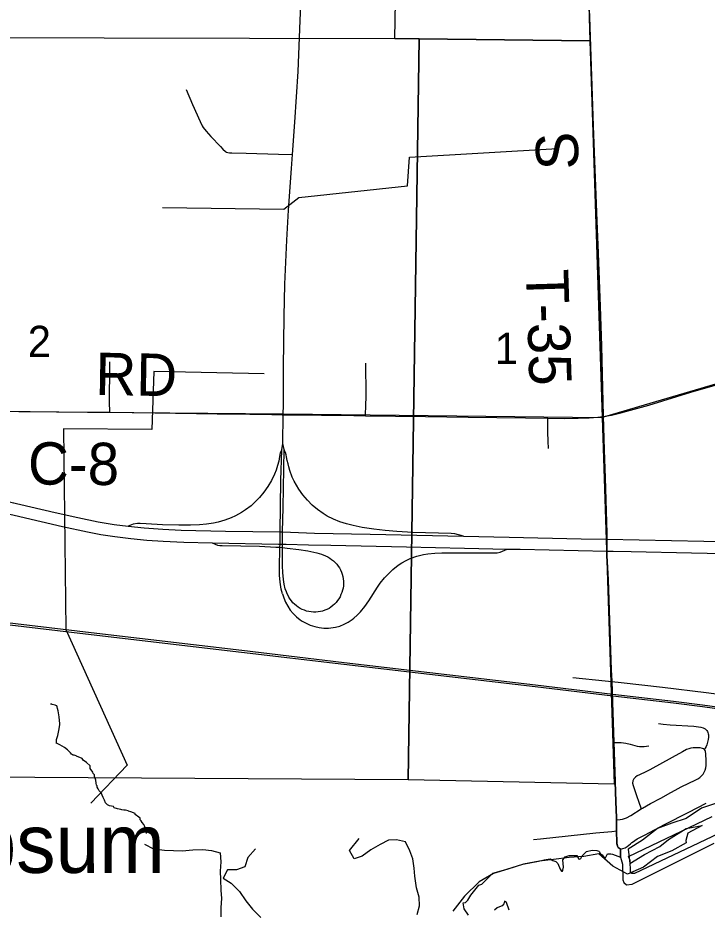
# Model space of a CAD drawing. Extents: x 63.4 to 97.4, y 0.4 to 22.4.
# Drawn here: x 67.186 to 68.112, y 15.396 to 16.594 of the extents above; entities that cross this region are included whole.
import ezdxf

# ---------------------------------------------------------------- set-up
doc = ezdxf.new("R2010")
doc.units = 0
for name, color, linetype in [('GM_X_County_Road', 7, 'Continuous'), ('GM_X_County_Road_Text', 7, 'Continuous'), ('GM_X_Interchange_Ramps', 7, 'Continuous'), ('GM_X_Major_Lake', 7, 'Continuous'), ('GM_X_Minor_River', 7, 'Continuous'), ('GM_X_Rail_Line', 7, 'Continuous'), ('GM_X_Section', 7, 'Continuous'), ('GM_X_Section_Text', 7, 'Continuous'), ('GM_X_State_Route', 7, 'Continuous'), ('GM_X_Township_Road', 7, 'Continuous'), ('GM_X_Township_Road_Text', 7, 'Continuous'), ('GM_X_Unincorporated_Text', 7, 'Continuous'), ('SH_Cut_Line', 7, 'Continuous')]:
    doc.layers.add(name, color=color, linetype=linetype)

msp = doc.modelspace()

# ---------------------------------------------------------------- linework, layer by layer
at = {"layer": 'GM_X_County_Road'}
for points in [[(67.7914, 15.3899), (67.7854, 15.3981), (67.7843, 15.4062), (67.7872, 15.4069), (67.7903, 15.4097), (67.7946, 15.4168), (67.8052, 15.4302), (67.8091, 15.4313), (67.8147, 15.4366), (67.8242, 15.446), (67.8431, 15.4517), (67.8644, 15.4581), (67.8856, 15.4623), (67.8932, 15.4641), (67.9011, 15.4652), (67.9045, 15.4632), (67.9061, 15.4629), (67.9088, 15.4618), (67.9112, 15.4591), (67.9143, 15.4515), (67.9161, 15.4489), (67.9176, 15.4488), (67.9182, 15.4502), (67.9188, 15.4544), (67.918, 15.4642), (67.921, 15.4681), (67.9266, 15.4698), (67.9369, 15.4699), (67.9376, 15.4685), (67.9392, 15.4655), (67.9405, 15.4648), (67.9424, 15.466), (67.944, 15.4694), (67.9497, 15.4754), (67.9576, 15.4771), (67.9639, 15.4764), (67.9663, 15.4757), (67.9672, 15.4747), (67.9681, 15.4725), (67.9708, 15.4709), (67.9735, 15.4673), (67.9749, 15.466), (67.9762, 15.4685), (67.978, 15.4723), (67.9825, 15.4723), (67.9849, 15.4715), (67.9953, 15.4677), (67.9954, 15.479), (67.9937, 15.4797), (67.9925, 15.4806), (67.9916, 15.4824), (67.9909, 15.4844), (67.9905, 15.4862), (67.9905, 15.488), (67.9903, 15.5018), (67.9903, 15.5034), (67.9902, 15.5183), (67.9902, 15.5204), (67.9892, 15.5422), (67.9866, 15.6219), (67.9849, 15.6757), (67.9838, 15.7038), (67.9831, 15.7192), (67.9813, 15.772), (67.979, 15.8401), (67.9773, 15.872), (67.9773, 15.8791), (67.9771, 15.895), (67.977, 15.9024), (67.9748, 15.9769), (67.9736, 16.0142), (67.9722, 16.0597), (67.9698, 16.154), (67.9682, 16.2068), (67.9653, 16.2782), (67.9637, 16.3217), (67.9589, 16.449), (67.9575, 16.4894), (67.954, 16.595)], [(67.954, 16.595), (67.9575, 16.4894), (67.9589, 16.449), (67.9637, 16.3217), (67.9653, 16.2782), (67.9682, 16.2068), (67.9698, 16.154), (67.9722, 16.0597), (67.9736, 16.0142), (67.9748, 15.9769), (67.977, 15.9024), (67.9771, 15.895), (67.9773, 15.8791), (67.9773, 15.872), (67.979, 15.8401), (67.9813, 15.772), (67.9831, 15.7192), (67.9838, 15.7038), (67.9849, 15.6757), (67.9866, 15.6219), (67.9892, 15.5422), (67.9902, 15.5204), (67.9902, 15.5183), (67.9903, 15.5034), (67.9903, 15.5018), (67.9905, 15.488), (67.9905, 15.4862), (67.9909, 15.4844), (67.9916, 15.4824), (67.9925, 15.4806), (67.9937, 15.4797), (67.9954, 15.479), (67.9953, 15.4677), (67.9984, 15.4584), (67.9986, 15.4373), (67.9999, 15.4336), (68.0036, 15.4304), (68.0113, 15.4313), (68.1213, 15.4865)], [(67.9724, 16.0591), (67.9774, 16.0599), (67.9835, 16.0611), (67.9961, 16.064), (68.0088, 16.0675), (68.0336, 16.0744), (68.09, 16.0918), (68.1165, 16.0994), (68.1264, 16.1022)], [(66.9594, 16.0695), (66.9875, 16.0692), (67.087, 16.0673), (67.2799, 16.0651), (67.3097, 16.0648)], [(67.3097, 16.0648), (67.3421, 16.0644), (67.4541, 16.0627), (67.4976, 16.0624), (67.5132, 16.0621), (67.5412, 16.0615), (67.5426, 16.0615)], [(67.5426, 16.0615), (67.594, 16.0609), (67.6376, 16.0604), (67.653, 16.0601)], [(67.653, 16.0601), (67.7335, 16.0591), (67.7908, 16.0584), (67.8679, 16.0574), (67.8979, 16.057)], [(67.8979, 16.057), (67.9204, 16.0566), (67.9388, 16.0567), (67.9534, 16.0573), (67.9649, 16.0583), (67.9724, 16.0591)], [(68.1268, 15.4988), (68.0141, 15.4455), (68.0109, 15.4455), (68.0088, 15.4478), (68.0086, 15.4633), (68.0063, 15.4683), (68.1184, 15.5224)], [(67.8462, 15.3963), (67.8426, 15.4066), (67.8398, 15.4087), (67.8387, 15.4048), (67.8366, 15.4023), (67.8331, 15.4009), (67.8299, 15.3995), (67.8264, 15.3963)]]:
    msp.add_lwpolyline(points, dxfattribs=at)
at = {"layer": 'GM_X_Interchange_Ramps'}
for points in [[(67.5407, 16.0143), (67.5387, 16.0105), (67.5377, 16.0054), (67.5366, 15.9993), (67.5351, 15.9932), (67.5332, 15.9873), (67.531, 15.9815), (67.5269, 15.973), (67.522, 15.965), (67.5166, 15.9574), (67.5106, 15.9502), (67.5041, 15.9435), (67.4994, 15.9394), (67.4919, 15.9338), (67.4867, 15.9303), (67.4785, 15.9258), (67.4728, 15.9231), (67.4641, 15.9198), (67.4551, 15.9173), (67.449, 15.916), (67.4397, 15.9147), (67.4304, 15.9139), (67.4179, 15.9134), (67.4023, 15.9133), (67.3805, 15.9139), (67.3587, 15.915), (67.3507, 15.9156), (67.3469, 15.9157), (67.3413, 15.9147), (67.3343, 15.9118)], [(67.7848, 15.8983), (67.773, 15.9015), (67.768, 15.9021), (67.7168, 15.9034), (67.6951, 15.9046), (67.6796, 15.9059), (67.6641, 15.9078), (67.6488, 15.9102), (67.6366, 15.9127), (67.6275, 15.915), (67.6187, 15.9178), (67.61, 15.9213), (67.6017, 15.9255), (67.5964, 15.9287), (67.5888, 15.9341), (67.5817, 15.9402), (67.5751, 15.9468), (67.5691, 15.9539), (67.5636, 15.9615), (67.5604, 15.9668), (67.5574, 15.9723), (67.5548, 15.9779), (67.5515, 15.9866), (67.5501, 15.9914), (67.5491, 15.9956), (67.5481, 16.0002), (67.5471, 16.0048), (67.5464, 16.0078), (67.5458, 16.0108), (67.5449, 16.0123), (67.5437, 16.0146)], [(67.5415, 15.821), (67.5433, 15.8156), (67.5457, 15.8098), (67.5486, 15.8044), (67.5521, 15.7992), (67.556, 15.7945), (67.5604, 15.7901), (67.5653, 15.7862), (67.5679, 15.7845), (67.5733, 15.7815), (67.579, 15.779), (67.5849, 15.7771), (67.5909, 15.7758), (67.5971, 15.7751), (67.6033, 15.7751), (67.6064, 15.7753), (67.6126, 15.7763), (67.6185, 15.7779), (67.6243, 15.7802), (67.6298, 15.7831), (67.635, 15.7865), (67.6374, 15.7884), (67.642, 15.7925), (67.6464, 15.797), (67.6522, 15.8042), (67.6575, 15.8119), (67.6694, 15.8302), (67.673, 15.8353), (67.6788, 15.8426), (67.6829, 15.8472), (67.6896, 15.8536), (67.6969, 15.8594), (67.7021, 15.8628), (67.7075, 15.8659), (67.7131, 15.8685), (67.7219, 15.8717), (67.7309, 15.8738), (67.737, 15.8748), (67.7463, 15.8757), (67.7556, 15.876), (67.7711, 15.8763), (67.8299, 15.8762), (67.8338, 15.877), (67.8433, 15.8812)]]:
    msp.add_lwpolyline(points, dxfattribs=at)
at = {"layer": 'GM_X_Major_Lake'}
for points in [[(68.1242, 15.5399), (68.1041, 15.5334), (68.0836, 15.5195), (68.0646, 15.5131), (68.0452, 15.506), (68.0251, 15.4905)], [(68.06, 15.4912), (68.0836, 15.506), (68.1052, 15.5099), (68.0858, 15.4996), (68.0832, 15.4902)], [(68.06, 15.4912), (68.0836, 15.506), (68.1052, 15.5099), (68.0858, 15.4996), (68.0832, 15.4902)], [(68.0832, 15.4902), (68.0837, 15.4869), (68.0643, 15.4761), (68.0453, 15.4686), (68.0263, 15.4542), (68.0047, 15.445), (67.9853, 15.4557), (67.9664, 15.4723), (67.9462, 15.4684)], [(68.0832, 15.4902), (68.0837, 15.4869), (68.0643, 15.4761), (68.0453, 15.4686), (68.0263, 15.4542), (68.0047, 15.445), (67.9853, 15.4557), (67.9664, 15.4723), (67.9462, 15.4684)], [(68.0251, 15.4905), (68.0058, 15.4784), (68.008, 15.4592), (68.0278, 15.4714), (68.0483, 15.4819), (68.06, 15.4912)], [(67.9462, 15.4684), (67.9264, 15.4672), (67.9056, 15.4645), (67.8866, 15.4623), (67.8653, 15.4581), (67.8441, 15.4516), (67.8251, 15.4459), (67.8057, 15.4345), (67.786, 15.4151), (67.7704, 15.3953)]]:
    msp.add_lwpolyline(points, dxfattribs=at)
at = {"layer": 'GM_X_Minor_River'}
for points in [[(67.3804, 16.3395), (67.5433, 16.3372), (67.5637, 16.3533), (67.7094, 16.3688), (67.7123, 16.4072), (67.9108, 16.4188)], [(67.5171, 16.1163), (67.369, 16.1194), (67.366, 16.0415), (67.2475, 16.0424), (67.2508, 15.773), (67.3329, 15.5913), (67.2842, 15.5401)], [(67.3592, 15.4992), (67.3588, 15.5015), (67.3581, 15.5034), (67.3581, 15.5045), (67.3574, 15.5068), (67.3563, 15.5095), (67.3556, 15.5114), (67.3533, 15.5141), (67.3519, 15.5164), (67.3507, 15.5179), (67.3504, 15.5198), (67.347, 15.5225), (67.3455, 15.5237), (67.344, 15.5248), (67.3437, 15.526), (67.338, 15.5283), (67.335, 15.5292), (67.3342, 15.5299), (67.3308, 15.5307), (67.3286, 15.5308), (67.3259, 15.5312), (67.3244, 15.5316), (67.3202, 15.5324), (67.3157, 15.534), (67.3146, 15.5355), (67.3093, 15.5367), (67.3067, 15.5379), (67.3055, 15.5391), (67.3041, 15.5406), (67.3026, 15.544), (67.3007, 15.5479), (67.2982, 15.554), (67.2956, 15.5567), (67.2941, 15.5594), (67.293, 15.5616), (67.2926, 15.5632), (67.2919, 15.5643), (67.2915, 15.567), (67.2908, 15.5708), (67.2901, 15.5735), (67.289, 15.5761), (67.2891, 15.578), (67.2876, 15.58), (67.2868, 15.5819), (67.2835, 15.5865), (67.2832, 15.5903), (67.2783, 15.5949), (67.2738, 15.598), (67.2727, 15.5999), (67.2652, 15.6031), (67.2648, 15.6038), (67.2618, 15.6046), (67.2606, 15.6046), (67.2603, 15.605), (67.2595, 15.605), (67.2584, 15.6058), (67.2569, 15.6077), (67.2558, 15.6089), (67.2531, 15.6116), (67.249, 15.6147), (67.2426, 15.6186), (67.2392, 15.6201), (67.2377, 15.6205), (67.2381, 15.6213), (67.2382, 15.6255), (67.2398, 15.6311), (67.2414, 15.6376), (67.2418, 15.6398), (67.2427, 15.6455), (67.2427, 15.6467), (67.2417, 15.6562), (67.2403, 15.6642), (67.2396, 15.6672), (67.2392, 15.6695), (67.2385, 15.6707), (67.2381, 15.6707), (67.2362, 15.6718), (67.2324, 15.6726), (67.2317, 15.673), (67.2302, 15.6731)], [(67.7224, 15.3905), (67.7257, 15.4022), (67.7252, 15.414), (67.7217, 15.4263), (67.7193, 15.4419), (67.7184, 15.453), (67.7168, 15.4652), (67.7125, 15.4763), (67.7067, 15.4882), (67.6949, 15.4908), (67.6839, 15.4903), (67.6727, 15.4848), (67.6604, 15.4775), (67.6488, 15.469), (67.6377, 15.4654), (67.6318, 15.4766), (67.6447, 15.4927)], [(67.3565, 15.485), (67.3686, 15.479), (67.383, 15.4772), (67.3952, 15.4765), (67.407, 15.4763), (67.4211, 15.4775), (67.4348, 15.4779), (67.4461, 15.4765), (67.4579, 15.4736), (67.4587, 15.4614), (67.4581, 15.4489), (67.4582, 15.4375), (67.459, 15.4234), (67.4596, 15.412), (67.4589, 15.4002), (67.459, 15.3876)], [(67.5056, 15.479), (67.495, 15.4671), (67.4909, 15.4546), (67.4798, 15.4507), (67.468, 15.4506), (67.4621, 15.4393), (67.4729, 15.4326), (67.4841, 15.4217), (67.4926, 15.409), (67.5015, 15.3977), (67.5126, 15.3868)]]:
    msp.add_lwpolyline(points, dxfattribs=at)
at = {"layer": 'GM_X_Rail_Line'}
for points in [[(65.5072, 16.0914), (66.1191, 16.083), (66.4239, 16.0787), (66.8313, 16.0688), (67.543, 16.0626), (67.9702, 16.0577), (68.6101, 16.2463), (69.1053, 16.3972), (70.1929, 16.7393), (70.2646, 16.7591), (70.3642, 16.7634), (70.5898, 16.7764), (70.6857, 16.8302), (70.7827, 16.8988), (71.2174, 17.2501), (71.5086, 17.4876), (71.6576, 17.6039), (72.13, 17.975), (72.3072, 18.116)], [(66.467, 15.8627), (66.8611, 15.8179), (66.9571, 15.8051), (67.0056, 15.7998), (67.2846, 15.7667), (67.4867, 15.743), (67.6241, 15.7268), (67.881, 15.6968), (67.9851, 15.6843), (68.0666, 15.6747), (68.1054, 15.67), (68.1409, 15.665)], [(66.4673, 15.865), (66.8614, 15.8202), (66.9574, 15.8074), (67.0058, 15.8021), (67.2848, 15.769), (67.487, 15.7453), (67.6243, 15.7291), (67.8813, 15.6991), (67.9854, 15.6866), (68.0669, 15.677), (68.1057, 15.6723), (68.1412, 15.6673)]]:
    msp.add_lwpolyline(points, dxfattribs=at)
at = {"layer": 'GM_X_Section'}
for points in [[(67.9257, 17.5727), (67.9544, 16.5634), (67.725, 16.5661), (67.6925, 16.5663), (67.711, 17.573)], [(67.725, 16.5661), (67.7104, 15.5714), (66.7072, 15.5775), (66.716, 16.5687), (67.6925, 16.5663)], [(67.9544, 16.5634), (67.987, 15.5655), (67.7104, 15.5714), (67.725, 16.5661)]]:
    msp.add_lwpolyline(points, close=True, dxfattribs=at)
at = {"layer": 'GM_X_State_Route'}
for p, q in [((67.4473, 15.8897), (67.5363, 15.8878)), ((67.5417, 15.8638), (67.5418, 15.883)), ((67.5467, 15.8876), (67.5766, 15.887)), ((67.5766, 15.887), (67.6065, 15.8863))]:
    msp.add_line(p, q, dxfattribs=at)
for points in [[(67.555, 16.4107), (67.5582, 16.4541), (67.5625, 16.5224), (67.5653, 16.5907), (67.5665, 16.6218), (67.568, 16.6653), (67.574, 16.8332), (67.5756, 16.8673), (67.5777, 16.9233), (67.5801, 16.9792), (67.5803, 16.984)], [(67.5426, 16.0615), (67.5428, 16.0752), (67.5428, 16.0908), (67.5431, 16.125), (67.5439, 16.1934), (67.5449, 16.2369), (67.5473, 16.2959), (67.5497, 16.3362), (67.5537, 16.3921), (67.555, 16.4107)], [(65.6038, 16.2956), (65.6724, 16.2794), (65.7663, 16.2577), (65.9296, 16.2191), (66.0598, 16.1888), (66.329, 16.126), (66.3474, 16.1217), (66.4927, 16.0876), (66.7984, 16.0161), (66.9588, 15.9785), (66.986, 15.9721), (67.2462, 15.9113), (67.2796, 15.9042), (67.2979, 15.9007), (67.3163, 15.8979), (67.3379, 15.8952), (67.3595, 15.8931), (67.3812, 15.8916), (67.4091, 15.8905), (67.4473, 15.8897)], [(66.4824, 16.1066), (66.9589, 15.9953), (67.0548, 15.9729), (67.1244, 15.9564), (67.2365, 15.9302), (67.2668, 15.9234), (67.2943, 15.9179), (67.3158, 15.9143), (67.3343, 15.9118), (67.356, 15.9097), (67.3809, 15.9078), (67.4058, 15.9067), (67.4649, 15.9054), (67.5385, 15.9041), (67.5418, 15.9041), (67.5848, 15.9026), (67.6594, 15.901), (67.7848, 15.8983)], [(67.5418, 15.8835), (67.5418, 15.885), (67.5418, 15.8877), (67.5418, 15.9041), (67.5425, 15.9368), (67.5437, 16.0146), (67.5421, 16.0227), (67.5426, 16.0615)], [(67.5415, 15.821), (67.5399, 15.8275), (67.5385, 15.8367), (67.5378, 15.846), (67.5376, 15.8553), (67.5382, 15.8835), (67.5383, 15.8878), (67.5384, 15.8926), (67.5385, 15.9041), (67.5395, 15.9733), (67.5407, 16.0143), (67.5421, 16.0227)], [(67.7848, 15.8983), (67.8461, 15.897), (67.9426, 15.8951), (67.9773, 15.8944)], [(67.9773, 15.8944), (68.1074, 15.8917), (68.1945, 15.8897)], [(67.4473, 15.8897), (67.4545, 15.8864), (67.4573, 15.886), (67.4607, 15.886), (67.5108, 15.885), (67.5326, 15.8839), (67.5382, 15.8835), (67.5418, 15.8833), (67.5481, 15.8826), (67.5635, 15.8808), (67.5757, 15.8786), (67.5879, 15.876), (67.5939, 15.8743), (67.5996, 15.872), (67.6024, 15.8706), (67.6051, 15.869), (67.6076, 15.8673), (67.61, 15.8653), (67.6123, 15.8632), (67.6144, 15.8609), (67.6163, 15.8584), (67.618, 15.8558), (67.6195, 15.8531), (67.6208, 15.8503), (67.6218, 15.8474), (67.6226, 15.8444), (67.6232, 15.8413), (67.6235, 15.8382), (67.6235, 15.8351), (67.6234, 15.832), (67.6229, 15.8289), (67.6222, 15.8259), (67.6213, 15.8229), (67.6202, 15.82), (67.6189, 15.8172), (67.6173, 15.8145), (67.6156, 15.812), (67.6136, 15.8095), (67.6115, 15.8073), (67.6092, 15.8052), (67.6067, 15.8033), (67.6041, 15.8016), (67.6013, 15.8002), (67.5985, 15.799), (67.5955, 15.798), (67.5925, 15.7972), (67.5895, 15.7968), (67.5864, 15.7965), (67.5833, 15.7965), (67.5802, 15.7968), (67.5771, 15.7973), (67.5741, 15.798), (67.5711, 15.799), (67.5682, 15.8002), (67.5655, 15.8016), (67.5628, 15.8032), (67.5603, 15.805), (67.5579, 15.807), (67.5557, 15.8092), (67.5537, 15.8115), (67.5518, 15.814), (67.5502, 15.8166), (67.5474, 15.8222), (67.5469, 15.8236), (67.5453, 15.828), (67.5438, 15.834), (67.5428, 15.8402), (67.542, 15.8495), (67.5417, 15.8588), (67.5417, 15.8638)], [(67.5363, 15.8878), (67.5383, 15.8878), (67.5418, 15.8877), (67.5467, 15.8876)], [(67.6065, 15.8863), (67.708, 15.8842), (67.7859, 15.8824), (67.8433, 15.8812)], [(67.8433, 15.8812), (67.8606, 15.8809), (67.9775, 15.8785), (67.9856, 15.8783)], [(67.9856, 15.8783), (68.01, 15.8778), (68.0909, 15.8761), (68.1968, 15.8738), (68.2092, 15.8735), (68.2404, 15.8723), (68.259, 15.8711), (68.2777, 15.8691), (68.2962, 15.8664), (68.3115, 15.8637), (68.3298, 15.8599), (68.348, 15.8554), (68.366, 15.8503), (68.3838, 15.8444), (68.4014, 15.8379), (68.4187, 15.8308), (68.4357, 15.823), (68.4524, 15.8146), (68.4689, 15.8057), (68.4824, 15.7976)]]:
    msp.add_lwpolyline(points, dxfattribs=at)
at = {"layer": 'GM_X_Township_Road'}
msp.add_line((67.9905, 15.5028), (67.9904, 15.5178), dxfattribs=at)
for points in [[(67.9724, 16.0591), (67.97, 16.1534), (67.9685, 16.2062), (67.9655, 16.2776), (67.9639, 16.3211), (67.9591, 16.4484), (67.9577, 16.4888), (67.9542, 16.5944), (67.9516, 16.6658), (67.9465, 16.8211), (67.9429, 16.9112), (67.9401, 16.9982), (67.9376, 17.0851), (67.9356, 17.1597), (67.9321, 17.2995), (67.9309, 17.3399), (67.9304, 17.3555)], [(67.4122, 16.498), (67.421, 16.478), (67.4309, 16.4551), (67.4337, 16.4495), (67.4353, 16.4469), (67.4391, 16.4419), (67.4455, 16.4351), (67.4584, 16.4215), (67.4617, 16.4178), (67.4649, 16.415), (67.4666, 16.4139), (67.4684, 16.4133), (67.4707, 16.4131), (67.4738, 16.413), (67.4928, 16.4125), (67.5365, 16.4112), (67.555, 16.4107)], [(67.3097, 16.0648), (67.3095, 16.0787), (67.3094, 16.085), (67.3098, 16.1194), (67.3098, 16.1323)], [(67.653, 16.0601), (67.6532, 16.0631), (67.6536, 16.0721), (67.6539, 16.0877), (67.6535, 16.1306)], [(67.8988, 16.0162), (67.8983, 16.0258), (67.8979, 16.0382), (67.8979, 16.057)], [(67.984, 15.7033), (67.9833, 15.7187), (67.9815, 15.7714), (67.9793, 15.8395), (67.9776, 15.8714), (67.9775, 15.8785), (67.9773, 15.8944), (67.9772, 15.9018), (67.975, 15.9764), (67.9738, 16.0136), (67.9724, 16.0591)], [(67.9316, 15.7088), (67.9748, 15.7042), (67.984, 15.7033)], [(67.9852, 15.6731), (67.9851, 15.6752), (67.984, 15.7033)], [(67.984, 15.7033), (67.9965, 15.702), (68.0521, 15.6957), (68.1107, 15.6887), (68.1445, 15.684), (68.1629, 15.6807), (68.2633, 15.6598), (68.288, 15.6545)], [(67.9904, 15.5178), (67.9904, 15.5199), (67.9894, 15.5416), (67.9869, 15.6214), (67.9852, 15.6731)], [(68.0467, 15.647), (68.0529, 15.646), (68.0623, 15.6451), (68.0939, 15.6434), (68.1002, 15.6427), (68.1033, 15.6421), (68.1063, 15.6411), (68.1091, 15.6397), (68.1105, 15.6387), (68.1114, 15.6376), (68.1123, 15.6364), (68.1129, 15.6349), (68.1134, 15.6333), (68.1136, 15.6318), (68.1136, 15.6286), (68.1132, 15.6255), (68.1125, 15.6218), (68.1114, 15.6186), (68.1105, 15.6162), (68.1093, 15.6139), (68.1081, 15.612)], [(67.9869, 15.6214), (67.9931, 15.6214), (67.9963, 15.6214), (67.9994, 15.6211), (68.0025, 15.6206), (68.0087, 15.6192), (68.0148, 15.6175), (68.0179, 15.6168), (68.021, 15.6163), (68.0241, 15.6161), (68.0273, 15.6162), (68.0304, 15.6166), (68.0335, 15.6172)], [(68.1081, 15.612), (68.1071, 15.6128), (68.1057, 15.6136), (68.1027, 15.6143), (68.0995, 15.6145), (68.0932, 15.6143), (68.0901, 15.6139), (68.0871, 15.6131), (68.0842, 15.612), (68.0786, 15.6091), (68.0651, 15.6014), (68.035, 15.5849), (68.0294, 15.5821), (68.0208, 15.5782), (68.0181, 15.5767), (68.0155, 15.5749), (68.0134, 15.5726), (68.012, 15.5699), (68.0117, 15.5669), (68.0123, 15.5638), (68.0174, 15.549), (68.0196, 15.5428), (68.0234, 15.5325)], [(68.0234, 15.5325), (68.025, 15.5335), (68.0358, 15.5397), (68.0497, 15.5468), (68.0632, 15.5546), (68.0687, 15.5577), (68.0769, 15.5621), (68.0967, 15.5713), (68.0995, 15.5728), (68.102, 15.5746), (68.1043, 15.5767), (68.1063, 15.5791), (68.108, 15.5817), (68.1092, 15.5846), (68.1101, 15.5876), (68.1105, 15.5907), (68.1105, 15.597), (68.1102, 15.6064), (68.1097, 15.6095), (68.109, 15.6108), (68.1081, 15.612)], [(67.9957, 15.4785), (67.9988, 15.4791), (68.0017, 15.4802), (68.0044, 15.4819), (68.0066, 15.4835), (68.0089, 15.4853), (68.0109, 15.4873), (68.0128, 15.4888), (68.0149, 15.4902), (68.0177, 15.4921), (68.0288, 15.4978), (68.0546, 15.5113), (68.0874, 15.528), (68.1105, 15.5401)], [(67.9904, 15.5178), (67.995, 15.5183), (67.998, 15.5186), (67.9995, 15.5189), (68.0008, 15.5193), (68.0037, 15.5205), (68.0092, 15.5235), (68.0234, 15.5325)], [(67.8787, 15.4914), (67.888, 15.4922), (67.9623, 15.5002), (67.984, 15.5022), (67.9905, 15.5028)], [(67.9957, 15.4785), (67.9939, 15.4792), (67.9927, 15.48), (67.9918, 15.4819), (67.9911, 15.4839), (67.9907, 15.4857), (67.9907, 15.4874), (67.9905, 15.5012), (67.9905, 15.5028)]]:
    msp.add_lwpolyline(points, dxfattribs=at)
at = {"layer": 'SH_Cut_Line'}
for points in [[(68.1268, 15.4988), (68.0141, 15.4455), (68.0109, 15.4455), (68.0088, 15.4478), (68.0086, 15.4633), (68.0063, 15.4683), (68.1184, 15.5224)], [(67.7914, 15.3899), (67.7854, 15.3981), (67.7843, 15.4062), (67.7872, 15.4069), (67.7903, 15.4097), (67.7946, 15.4168), (67.8052, 15.4302), (67.8091, 15.4313), (67.8147, 15.4366), (67.8242, 15.446), (67.8431, 15.4517), (67.8644, 15.4581), (67.8856, 15.4623), (67.8932, 15.4641), (67.9011, 15.4652), (67.9045, 15.4632), (67.9061, 15.4629), (67.9088, 15.4618), (67.9112, 15.4591), (67.9143, 15.4515), (67.9161, 15.4489), (67.9176, 15.4488), (67.9182, 15.4502), (67.9188, 15.4544), (67.918, 15.4642), (67.921, 15.4681), (67.9266, 15.4698), (67.9369, 15.4699), (67.9376, 15.4685), (67.9392, 15.4655), (67.9405, 15.4648), (67.9424, 15.466), (67.944, 15.4694), (67.9497, 15.4754), (67.9576, 15.4771), (67.9639, 15.4764), (67.9663, 15.4757), (67.9672, 15.4747), (67.9681, 15.4725), (67.9708, 15.4709), (67.9735, 15.4673), (67.9749, 15.466), (67.9762, 15.4685), (67.978, 15.4723), (67.9825, 15.4723), (67.9849, 15.4715), (67.9953, 15.4677), (67.9984, 15.4584), (67.9986, 15.4373), (67.9999, 15.4336), (68.0036, 15.4304), (68.0113, 15.4313), (68.1213, 15.4865)], [(67.8462, 15.3963), (67.8426, 15.4066), (67.8398, 15.4087), (67.8387, 15.4048), (67.8366, 15.4023), (67.8331, 15.4009), (67.8299, 15.3995), (67.8264, 15.3963)]]:
    msp.add_lwpolyline(points, dxfattribs=at)

# ---------------------------------------------------------------- texts
at = {"layer": 'GM_X_County_Road_Text'}
for s, rotation, p in [('RD', 359.0178, (67.29, 16.0881)), ('C-8', 359.541, (67.1997, 15.9679))]:
    msp.add_text(s, height=0.05682, rotation=rotation, dxfattribs=at).set_placement(p)
at = {"layer": 'GM_X_Section_Text'}
for s, p in [('2', (67.1996, 16.139)), ('1', (67.8267, 16.1296))]:
    msp.add_text(s, height=0.0419, rotation=0, dxfattribs=at).set_placement(p)
at = {"layer": 'GM_X_Township_Road_Text'}
for s, height, rotation, p in [('S', 0.0568, 92.4881, (67.9398, 16.3914)), ('T-35', 0.05682, 271.7685, (67.8685, 16.256))]:
    msp.add_text(s, height=height, rotation=rotation, dxfattribs=at).set_placement(p)
at = {"layer": 'GM_X_Unincorporated_Text'}
msp.add_text('Gypsum', height=0.07898, rotation=0, dxfattribs=at).set_placement((66.9904, 15.4465))

doc.saveas('drawing.dxf')
